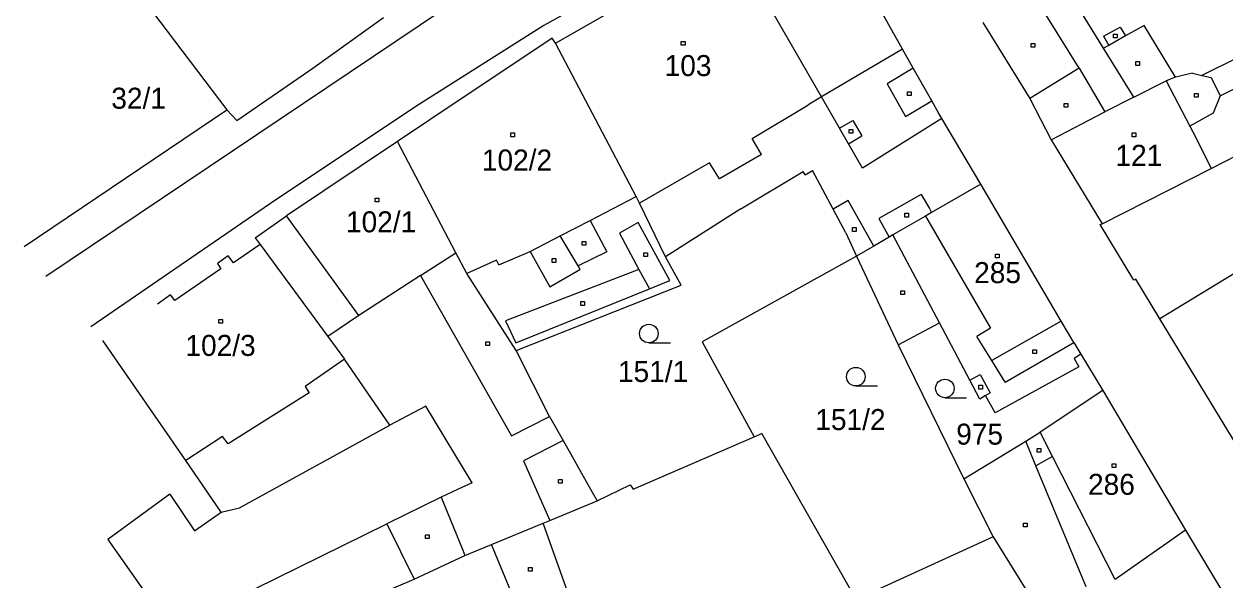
# Model space of a CAD drawing. Extents: x -711879 to -711361, y -1048782 to -1048177.
# Drawn here: x -711816.1 to -711718.9, y -1048658.1 to -1048613.1 of the extents above; entities that cross this region are included whole.
import ezdxf

# ---------------------------------------------------------------- set-up
doc = ezdxf.new("R2010")
doc.units = 0
for name, color, linetype in [('Vrstva 1', 7, 'Continuous'), ('Vrstva 14', 7, 'Continuous'), ('Vrstva 15', 7, 'Continuous'), ('Vrstva 2', 7, 'Continuous'), ('Vrstva 23', 7, 'Continuous'), ('Vrstva 25', 7, 'Continuous'), ('Vrstva 46', 7, 'Continuous')]:
    doc.layers.add(name, color=color, linetype=linetype)

msp = doc.modelspace()

# ---------------------------------------------------------------- linework, layer by layer
at = {"layer": 'Vrstva 1'}
for p, q in [((-711744.94, -1048615.17), (-711751.91, -1048602.81)), ((-711773.03, -1048614.7), (-711758.74, -1048606.51)), ((-711751.49, -1048619.05), (-711758.65, -1048606.65)), ((-711728.66, -1048615.1), (-711732.3, -1048609.22)), ((-711806.26, -1048611.37), (-711799.65, -1048620.09)), ((-711792.69, -1048616.72), (-711786.97, -1048612.61)), ((-711738.43, -1048613.03), (-711734.62, -1048619.17)), ((-711773.3, -1048614.29), (-711783.21, -1048620.9)), ((-711773.03, -1048614.7), (-711773.3, -1048614.29)), ((-711766.51, -1048627.1), (-711773.03, -1048614.7)), ((-711744.07, -1048616.71), (-711744.94, -1048615.17)), ((-711726.2, -1048619.07), (-711728.66, -1048615.1)), ((-711798.83, -1048620.94), (-711792.69, -1048616.72)), ((-711742.57, -1048619.36), (-711744.07, -1048616.71)), ((-711717.7, -1048615.82), (-711720.7, -1048617.31)), ((-711726.2, -1048619.07), (-711723.6, -1048617.74)), ((-711722.84, -1048617.45), (-711723.6, -1048617.74)), ((-711721.47, -1048617.13), (-711722.84, -1048617.45)), ((-711721.47, -1048617.13), (-711720.7, -1048617.31)), ((-711719.96, -1048624.83), (-711707.96, -1048618.7)), ((-711750.04, -1048621.56), (-711751.49, -1048619.05)), ((-711741.99, -1048620.39), (-711742.57, -1048619.36)), ((-711734.62, -1048619.17), (-711732.9, -1048622.51)), ((-711726.2, -1048619.07), (-711728.56, -1048620.25)), ((-711816.07, -1048631.14), (-711799.65, -1048620.09)), ((-711799.65, -1048620.09), (-711798.83, -1048620.94)), ((-711741.76, -1048620.78), (-711741.99, -1048620.39)), ((-711732.9, -1048622.51), (-711728.56, -1048620.25)), ((-711783.21, -1048620.9), (-711785.83, -1048622.65)), ((-711749.3, -1048622.85), (-711750.04, -1048621.56)), ((-711741.76, -1048620.78), (-711748.17, -1048624.8)), ((-711738.61, -1048626.11), (-711741.76, -1048620.78)), ((-711732.9, -1048622.51), (-711728.77, -1048629.3)), ((-711785.83, -1048622.65), (-711794.82, -1048628.67)), ((-711781.1, -1048631.65), (-711785.83, -1048622.65)), ((-711748.17, -1048624.8), (-711749.3, -1048622.85)), ((-711758.03, -1048628.11), (-711752.99, -1048625.07)), ((-711752.83, -1048625.35), (-711752.99, -1048625.07)), ((-711752.83, -1048625.35), (-711752.24, -1048625)), ((-711750.56, -1048628.12), (-711752.24, -1048625)), ((-711728.77, -1048629.3), (-711719.96, -1048624.83)), ((-711738.61, -1048626.11), (-711742.58, -1048628.4)), ((-711732.1, -1048637.18), (-711738.61, -1048626.11)), ((-711766.23, -1048627.63), (-711766.51, -1048627.1)), ((-711764.13, -1048631.98), (-711766.23, -1048627.63)), ((-711758.03, -1048628.11), (-711764.13, -1048631.98)), ((-711749.53, -1048630.05), (-711750.56, -1048628.12)), ((-711742.58, -1048628.4), (-711743.07, -1048628.68)), ((-711797.34, -1048630.45), (-711794.82, -1048628.67)), ((-711743.07, -1048628.68), (-711745.72, -1048630.21)), ((-711728.94, -1048629.38), (-711728.77, -1048629.3)), ((-711726.21, -1048633.88), (-711728.94, -1048629.38)), ((-711711.1, -1048629.08), (-711724.1, -1048636.99)), ((-711749.53, -1048630.05), (-711748.66, -1048631.92)), ((-711746.02, -1048630.38), (-711747.26, -1048631.11)), ((-711745.72, -1048630.21), (-711746.02, -1048630.38)), ((-711796.94, -1048630.99), (-711799.12, -1048632.47)), ((-711797.34, -1048630.45), (-711796.94, -1048630.99)), ((-711796.94, -1048630.99), (-711791.47, -1048638.43)), ((-711747.26, -1048631.11), (-711748.66, -1048631.92)), ((-711799.53, -1048631.89), (-711800.4, -1048632.53)), ((-711799.12, -1048632.47), (-711799.53, -1048631.89)), ((-711780.21, -1048633.34), (-711781.1, -1048631.65)), ((-711762.87, -1048634.28), (-711764.13, -1048631.98)), ((-711748.66, -1048631.92), (-711761.17, -1048638.85)), ((-711748.66, -1048631.92), (-711745.29, -1048639.11)), ((-711800.12, -1048632.96), (-711803.87, -1048635.51)), ((-711800.4, -1048632.53), (-711800.12, -1048632.96)), ((-711776.21, -1048639.55), (-711780.21, -1048633.34)), ((-711726.04, -1048633.8), (-711726.21, -1048633.88)), ((-711724.1, -1048636.99), (-711726.04, -1048633.8)), ((-711804.21, -1048635.06), (-711805.25, -1048635.82)), ((-711803.87, -1048635.51), (-711804.21, -1048635.06)), ((-711776.21, -1048639.55), (-711762.87, -1048634.28)), ((-711731.08, -1048638.91), (-711732.1, -1048637.18)), ((-711717.47, -1048647.9), (-711724.1, -1048636.99)), ((-711745.29, -1048639.11), (-711741.95, -1048637.33)), ((-711739.5, -1048641.97), (-711741.95, -1048637.33)), ((-711802.98, -1048648.46), (-711809.68, -1048638.76)), ((-711791.47, -1048638.43), (-711790.13, -1048640.26)), ((-711761.17, -1048638.85), (-711756.96, -1048646.56)), ((-711745.29, -1048639.11), (-711739.97, -1048649.94)), ((-711731.08, -1048638.91), (-711730.51, -1048639.87)), ((-711773.53, -1048644.89), (-711776.21, -1048639.55)), ((-711730.51, -1048639.87), (-711731.04, -1048640.22)), ((-711730.51, -1048639.87), (-711728.73, -1048642.81)), ((-711786.45, -1048645.6), (-711790.13, -1048640.26)), ((-711730.66, -1048640.89), (-711737.44, -1048644.6)), ((-711731.04, -1048640.22), (-711730.66, -1048640.89)), ((-711738.69, -1048643.5), (-711739.5, -1048641.97)), ((-711728.73, -1048642.81), (-711733.79, -1048646.18)), ((-711728.73, -1048642.81), (-711722.03, -1048654.1)), ((-711738.22, -1048643.21), (-711738.69, -1048643.5)), ((-711737.44, -1048644.6), (-711738.22, -1048643.21)), ((-711783.53, -1048644.06), (-711786.45, -1048645.6)), ((-711779.78, -1048650.28), (-711783.53, -1048644.06)), ((-711773.53, -1048644.89), (-711772.42, -1048646.85)), ((-711798.61, -1048652.29), (-711786.45, -1048645.6)), ((-711772.42, -1048646.85), (-711770.06, -1048651.03)), ((-711766.76, -1048650.79), (-711756.96, -1048646.56)), ((-711756.96, -1048646.56), (-711756.32, -1048646.29)), ((-711748.69, -1048659.7), (-711756.32, -1048646.29)), ((-711739.97, -1048649.94), (-711734.95, -1048646.89)), ((-711734.95, -1048646.89), (-711733.79, -1048646.18)), ((-711800.1, -1048652.63), (-711802.98, -1048648.46)), ((-711780.91, -1048650.79), (-711782.28, -1048651.42)), ((-711779.78, -1048650.28), (-711780.91, -1048650.79)), ((-711769.66, -1048651.73), (-711766.98, -1048650.44)), ((-711766.98, -1048650.44), (-711766.76, -1048650.79)), ((-711739.97, -1048649.94), (-711737.61, -1048654.63)), ((-711782.28, -1048651.42), (-711786.69, -1048653.59)), ((-711773.5, -1048653.31), (-711769.66, -1048651.73)), ((-711770.06, -1048651.03), (-711769.66, -1048651.73)), ((-711800.1, -1048652.63), (-711798.61, -1048652.29)), ((-711786.69, -1048653.59), (-711784.49, -1048658.06)), ((-711778.21, -1048655.25), (-711774.04, -1048653.53)), ((-711774.04, -1048653.53), (-711773.5, -1048653.31)), ((-711771.92, -1048659.43), (-711774.04, -1048653.53)), ((-711737.61, -1048654.63), (-711748.69, -1048659.7)), ((-711737.61, -1048654.63), (-711734.47, -1048659.69)), ((-711722.03, -1048654.1), (-711717.9, -1048660.95)), ((-711780.37, -1048656.14), (-711778.21, -1048655.25)), ((-711784.49, -1048658.06), (-711780.37, -1048656.14)), ((-711792.84, -1048661.61), (-711784.49, -1048658.06))]:
    msp.add_line(p, q, dxfattribs=at)
at = {"layer": 'Vrstva 2'}
for p, q in [((-711759.6, -1048605.21), (-711773.98, -1048613.26)), ((-711730.65, -1048616.71), (-711734.44, -1048610.58)), ((-711814.29, -1048633.54), (-711782.1, -1048611.94)), ((-711773.98, -1048613.26), (-711784.05, -1048619.64)), ((-711728.66, -1048614.13), (-711727.32, -1048613.39)), ((-711727.32, -1048613.39), (-711726.88, -1048614.11)), ((-711725.37, -1048613.27), (-711726.88, -1048614.11)), ((-711722.84, -1048617.45), (-711725.37, -1048613.27)), ((-711728.66, -1048614.13), (-711728.24, -1048614.87)), ((-711726.88, -1048614.11), (-711728.24, -1048614.87)), ((-711744.94, -1048615.17), (-711751.49, -1048619.05)), ((-711728.24, -1048614.87), (-711728.66, -1048615.1)), ((-711744.07, -1048616.71), (-711746.18, -1048617.99)), ((-711730.65, -1048616.71), (-711734.62, -1048619.17)), ((-711730.65, -1048616.71), (-711728.56, -1048620.25)), ((-711723.6, -1048617.74), (-711721.67, -1048621.42)), ((-711720.7, -1048617.31), (-711719.96, -1048617.48)), ((-711719.96, -1048617.48), (-711719.23, -1048618.96)), ((-711719.23, -1048618.96), (-711716.76, -1048617.74)), ((-711746.18, -1048617.99), (-711744.69, -1048620.63)), ((-711784.05, -1048619.64), (-711795.68, -1048627.37)), ((-711751.49, -1048619.05), (-711752.6, -1048619.71)), ((-711744.69, -1048620.63), (-711742.57, -1048619.36)), ((-711719.23, -1048618.96), (-711719.79, -1048620.36)), ((-711757.12, -1048622.42), (-711752.6, -1048619.71)), ((-711719.79, -1048620.36), (-711721.67, -1048621.42)), ((-711750.04, -1048621.56), (-711748.96, -1048620.94)), ((-711748.96, -1048620.94), (-711748.24, -1048622.19)), ((-711721.67, -1048621.42), (-711721.19, -1048622.34)), ((-711756.37, -1048623.69), (-711757.12, -1048622.42)), ((-711749.3, -1048622.85), (-711748.24, -1048622.19)), ((-711721.19, -1048622.34), (-711719.96, -1048624.83)), ((-711760.57, -1048624.37), (-711766.23, -1048627.63)), ((-711759.76, -1048625.67), (-711760.57, -1048624.37)), ((-711756.37, -1048623.69), (-711759.76, -1048625.67)), ((-711795.68, -1048627.37), (-711810.66, -1048637.64)), ((-711770.23, -1048629.03), (-711766.51, -1048627.1)), ((-711749.33, -1048627.42), (-711750.56, -1048628.12)), ((-711747.26, -1048631.11), (-711749.33, -1048627.42)), ((-711743.42, -1048626.93), (-711746.85, -1048628.88)), ((-711743.42, -1048626.93), (-711742.76, -1048628.07)), ((-711742.76, -1048628.07), (-711742.58, -1048628.4)), ((-711788.95, -1048636.74), (-711794.82, -1048628.67)), ((-711772.65, -1048630.28), (-711770.23, -1048629.03)), ((-711770.23, -1048629.03), (-711768.89, -1048631.59)), ((-711766.34, -1048629.21), (-711767.86, -1048630.06)), ((-711763.79, -1048633.9), (-711766.34, -1048629.21)), ((-711746.85, -1048628.88), (-711746.02, -1048630.38)), ((-711743.07, -1048628.68), (-711737.82, -1048637.75)), ((-711775.1, -1048631.55), (-711772.65, -1048630.28)), ((-711771.21, -1048632.71), (-711772.65, -1048630.28)), ((-711767.86, -1048630.06), (-711766.29, -1048633.02)), ((-711741.95, -1048637.33), (-711745.72, -1048630.21)), ((-711783.96, -1048633.5), (-711781.1, -1048631.65)), ((-711777.82, -1048632.24), (-711780.21, -1048633.34)), ((-711777.63, -1048632.63), (-711777.82, -1048632.24)), ((-711777.63, -1048632.63), (-711775.1, -1048631.55)), ((-711775.1, -1048631.55), (-711773.49, -1048634.41)), ((-711768.89, -1048631.59), (-711771.21, -1048632.71)), ((-711766.29, -1048633.02), (-711777.09, -1048637.15)), ((-711773.49, -1048634.41), (-711771.06, -1048633.02)), ((-711771.21, -1048632.71), (-711771.06, -1048633.02)), ((-711766.29, -1048633.02), (-711765.42, -1048634.58)), ((-711783.96, -1048633.5), (-711788.95, -1048636.74)), ((-711783.96, -1048633.5), (-711776.59, -1048646.46)), ((-711765.42, -1048634.58), (-711763.79, -1048633.9)), ((-711776.24, -1048638.93), (-711765.42, -1048634.58)), ((-711788.95, -1048636.74), (-711791.47, -1048638.43)), ((-711777.09, -1048637.15), (-711776.24, -1048638.93)), ((-711732.1, -1048637.18), (-711737.71, -1048640.37)), ((-711737.82, -1048637.75), (-711738.91, -1048638.43)), ((-711737.71, -1048640.37), (-711738.91, -1048638.43)), ((-711736.64, -1048642.12), (-711731.08, -1048638.91)), ((-711790.13, -1048640.26), (-711793.3, -1048642.47)), ((-711736.64, -1048642.12), (-711737.71, -1048640.37)), ((-711739.5, -1048641.97), (-711738.64, -1048641.5)), ((-711738.64, -1048641.5), (-711737.84, -1048642.98)), ((-711792.98, -1048642.98), (-711799.55, -1048647.12)), ((-711793.3, -1048642.47), (-711792.98, -1048642.98)), ((-711738.22, -1048643.21), (-711737.84, -1048642.98)), ((-711776.59, -1048646.46), (-711773.53, -1048644.89)), ((-711800.01, -1048646.52), (-711802.98, -1048648.46)), ((-711799.55, -1048647.12), (-711800.01, -1048646.52)), ((-711772.42, -1048646.85), (-711775.64, -1048648.48)), ((-711734.14, -1048648.9), (-711734.95, -1048646.89)), ((-711732.79, -1048648.14), (-711733.79, -1048646.18)), ((-711775.64, -1048648.48), (-711773.5, -1048653.31)), ((-711732.79, -1048648.14), (-711734.14, -1048648.9)), ((-711727.73, -1048658.09), (-711732.79, -1048648.14)), ((-711730.06, -1048658.68), (-711734.14, -1048648.9)), ((-711804.26, -1048651.18), (-711809.27, -1048654.86)), ((-711804.26, -1048651.18), (-711802.27, -1048654.16)), ((-711782.28, -1048651.42), (-711780.54, -1048655.73)), ((-711802.27, -1048654.16), (-711800.1, -1048652.63)), ((-711799.14, -1048659.71), (-711786.69, -1048653.59)), ((-711722.03, -1048654.1), (-711727.73, -1048658.09)), ((-711809.27, -1048654.86), (-711804.42, -1048661.76)), ((-711776.33, -1048659.82), (-711778.21, -1048655.25)), ((-711780.54, -1048655.73), (-711780.37, -1048656.14))]:
    msp.add_line(p, q, dxfattribs=at)
at = {"layer": 'Vrstva 23'}
for p, q in [((-711765.48, -1048638.94), (-711763.73, -1048638.94)), ((-711748.72, -1048642.43), (-711746.97, -1048642.43)), ((-711741.51, -1048643.38), (-711739.76, -1048643.38))]:
    msp.add_line(p, q, dxfattribs=at)
for centre in [(-711765.48, -1048638.19), (-711748.72, -1048641.68), (-711741.51, -1048642.63)]:
    msp.add_circle(centre, 0.75, dxfattribs=at)
at = {"layer": 'Vrstva 25'}
for p, q in [((-711762.85, -1048614.55), (-711762.55, -1048614.55)), ((-711762.85, -1048614.85), (-711762.85, -1048614.55)), ((-711762.55, -1048614.55), (-711762.55, -1048614.85)), ((-711734.53, -1048614.72), (-711734.23, -1048614.72)), ((-711734.53, -1048615.02), (-711734.53, -1048614.72)), ((-711734.23, -1048614.72), (-711734.23, -1048615.02)), ((-711727.86, -1048613.97), (-711727.56, -1048613.97)), ((-711727.86, -1048614.27), (-711727.86, -1048613.97)), ((-711727.56, -1048614.27), (-711727.86, -1048614.27)), ((-711727.56, -1048613.97), (-711727.56, -1048614.27)), ((-711762.55, -1048614.85), (-711762.85, -1048614.85)), ((-711734.23, -1048615.02), (-711734.53, -1048615.02)), ((-711726.05, -1048616.19), (-711725.75, -1048616.19)), ((-711726.05, -1048616.49), (-711726.05, -1048616.19)), ((-711725.75, -1048616.49), (-711726.05, -1048616.49)), ((-711725.75, -1048616.19), (-711725.75, -1048616.49)), ((-711744.54, -1048618.64), (-711744.24, -1048618.64)), ((-711744.54, -1048618.94), (-711744.54, -1048618.64)), ((-711744.24, -1048618.64), (-711744.24, -1048618.94)), ((-711744.24, -1048618.94), (-711744.54, -1048618.94)), ((-711731.86, -1048619.57), (-711731.56, -1048619.57)), ((-711731.86, -1048619.87), (-711731.86, -1048619.57)), ((-711731.56, -1048619.57), (-711731.56, -1048619.87)), ((-711721.3, -1048618.76), (-711721, -1048618.76)), ((-711721.3, -1048619.06), (-711721.3, -1048618.76)), ((-711721, -1048619.06), (-711721.3, -1048619.06)), ((-711721, -1048618.76), (-711721, -1048619.06)), ((-711731.56, -1048619.87), (-711731.86, -1048619.87)), ((-711776.66, -1048621.96), (-711776.36, -1048621.96)), ((-711776.66, -1048622.26), (-711776.66, -1048621.96)), ((-711776.36, -1048622.26), (-711776.66, -1048622.26)), ((-711776.36, -1048621.96), (-711776.36, -1048622.26)), ((-711749.25, -1048621.67), (-711748.95, -1048621.67)), ((-711749.25, -1048621.97), (-711749.25, -1048621.67)), ((-711748.95, -1048621.97), (-711749.25, -1048621.97)), ((-711748.95, -1048621.67), (-711748.95, -1048621.97)), ((-711726.35, -1048621.96), (-711726.05, -1048621.96)), ((-711726.35, -1048622.26), (-711726.35, -1048621.96)), ((-711726.05, -1048622.26), (-711726.35, -1048622.26)), ((-711726.05, -1048621.96), (-711726.05, -1048622.26)), ((-711787.65, -1048627.24), (-711787.35, -1048627.24)), ((-711787.65, -1048627.54), (-711787.65, -1048627.24)), ((-711787.35, -1048627.24), (-711787.35, -1048627.54)), ((-711787.35, -1048627.54), (-711787.65, -1048627.54)), ((-711744.75, -1048628.46), (-711744.45, -1048628.46)), ((-711744.75, -1048628.76), (-711744.75, -1048628.46)), ((-711744.45, -1048628.76), (-711744.75, -1048628.76)), ((-711744.45, -1048628.46), (-711744.45, -1048628.76)), ((-711749, -1048629.62), (-711748.7, -1048629.62)), ((-711749, -1048629.92), (-711749, -1048629.62)), ((-711748.7, -1048629.92), (-711749, -1048629.92)), ((-711748.7, -1048629.62), (-711748.7, -1048629.92)), ((-711770.87, -1048630.74), (-711770.57, -1048630.74)), ((-711770.87, -1048631.04), (-711770.87, -1048630.74)), ((-711770.57, -1048631.04), (-711770.87, -1048631.04)), ((-711770.57, -1048630.74), (-711770.57, -1048631.04)), ((-711773.31, -1048632.13), (-711773.01, -1048632.13)), ((-711773.31, -1048632.43), (-711773.31, -1048632.13)), ((-711773.01, -1048632.13), (-711773.01, -1048632.43)), ((-711765.89, -1048631.66), (-711765.59, -1048631.66)), ((-711765.89, -1048631.96), (-711765.89, -1048631.66)), ((-711765.59, -1048631.96), (-711765.89, -1048631.96)), ((-711765.59, -1048631.66), (-711765.59, -1048631.96)), ((-711737.42, -1048631.76), (-711737.12, -1048631.76)), ((-711737.42, -1048632.06), (-711737.42, -1048631.76)), ((-711737.12, -1048632.06), (-711737.42, -1048632.06)), ((-711737.12, -1048631.76), (-711737.12, -1048632.06)), ((-711773.01, -1048632.43), (-711773.31, -1048632.43)), ((-711745.07, -1048634.73), (-711744.77, -1048634.73)), ((-711745.07, -1048635.03), (-711745.07, -1048634.73)), ((-711744.77, -1048635.03), (-711745.07, -1048635.03)), ((-711744.77, -1048634.73), (-711744.77, -1048635.03)), ((-711770.99, -1048635.61), (-711770.69, -1048635.61)), ((-711770.99, -1048635.91), (-711770.99, -1048635.61)), ((-711770.69, -1048635.91), (-711770.99, -1048635.91)), ((-711770.69, -1048635.61), (-711770.69, -1048635.91)), ((-711800.29, -1048637.06), (-711799.99, -1048637.06)), ((-711800.29, -1048637.36), (-711800.29, -1048637.06)), ((-711799.99, -1048637.06), (-711799.99, -1048637.36)), ((-711799.99, -1048637.36), (-711800.29, -1048637.36)), ((-711778.69, -1048638.87), (-711778.39, -1048638.87)), ((-711778.69, -1048639.17), (-711778.69, -1048638.87)), ((-711778.39, -1048638.87), (-711778.39, -1048639.17)), ((-711778.39, -1048639.17), (-711778.69, -1048639.17)), ((-711734.4, -1048639.51), (-711734.1, -1048639.51)), ((-711734.4, -1048639.81), (-711734.4, -1048639.51)), ((-711734.1, -1048639.81), (-711734.4, -1048639.81)), ((-711734.1, -1048639.51), (-711734.1, -1048639.81)), ((-711738.76, -1048642.38), (-711738.46, -1048642.38)), ((-711738.76, -1048642.68), (-711738.76, -1048642.38)), ((-711738.46, -1048642.68), (-711738.76, -1048642.68)), ((-711738.46, -1048642.38), (-711738.46, -1048642.68)), ((-711734.04, -1048647.48), (-711733.74, -1048647.48)), ((-711734.04, -1048647.78), (-711734.04, -1048647.48)), ((-711733.74, -1048647.78), (-711734.04, -1048647.78)), ((-711733.74, -1048647.48), (-711733.74, -1048647.78)), ((-711727.97, -1048648.74), (-711727.67, -1048648.74)), ((-711727.97, -1048649.04), (-711727.97, -1048648.74)), ((-711727.67, -1048648.74), (-711727.67, -1048649.04)), ((-711727.67, -1048649.04), (-711727.97, -1048649.04)), ((-711772.79, -1048649.99), (-711772.49, -1048649.99)), ((-711772.79, -1048650.29), (-711772.79, -1048649.99)), ((-711772.49, -1048650.29), (-711772.79, -1048650.29)), ((-711772.49, -1048649.99), (-711772.49, -1048650.29)), ((-711735.14, -1048653.53), (-711734.84, -1048653.53)), ((-711735.14, -1048653.83), (-711735.14, -1048653.53)), ((-711734.84, -1048653.53), (-711734.84, -1048653.83)), ((-711783.56, -1048654.47), (-711783.26, -1048654.47)), ((-711783.56, -1048654.77), (-711783.56, -1048654.47)), ((-711783.26, -1048654.47), (-711783.26, -1048654.77)), ((-711734.84, -1048653.83), (-711735.14, -1048653.83)), ((-711783.26, -1048654.77), (-711783.56, -1048654.77)), ((-711775.22, -1048657.11), (-711774.92, -1048657.11)), ((-711775.22, -1048657.41), (-711775.22, -1048657.11)), ((-711774.92, -1048657.41), (-711775.22, -1048657.41)), ((-711774.92, -1048657.11), (-711774.92, -1048657.41))]:
    msp.add_line(p, q, dxfattribs=at)
at = {"layer": 'Vrstva 46'}
for p, q in [((-711728.66, -1048615.1), (-711728.66, -1048615.1)), ((-711792.69, -1048616.72), (-711792.69, -1048616.72)), ((-711730.65, -1048616.71), (-711730.65, -1048616.71)), ((-711723.6, -1048617.74), (-711723.6, -1048617.74)), ((-711721.47, -1048617.13), (-711721.47, -1048617.13)), ((-711720.7, -1048617.31), (-711720.7, -1048617.31)), ((-711719.96, -1048617.48), (-711719.96, -1048617.48)), ((-711734.62, -1048619.17), (-711734.62, -1048619.17)), ((-711726.2, -1048619.07), (-711726.2, -1048619.07)), ((-711719.23, -1048618.96), (-711719.23, -1048618.96)), ((-711732.9, -1048622.51), (-711732.9, -1048622.51)), ((-711756.37, -1048623.69), (-711756.37, -1048623.69)), ((-711719.96, -1048624.83), (-711719.96, -1048624.83)), ((-711759.76, -1048625.67), (-711759.76, -1048625.67)), ((-711758.03, -1048628.11), (-711758.03, -1048628.11)), ((-711728.94, -1048629.38), (-711728.94, -1048629.38)), ((-711728.77, -1048629.3), (-711728.77, -1048629.3)), ((-711775.1, -1048631.55), (-711775.1, -1048631.55)), ((-711777.63, -1048632.63), (-711777.63, -1048632.63)), ((-711771.06, -1048633.02), (-711771.06, -1048633.02)), ((-711783.96, -1048633.5), (-711783.96, -1048633.5)), ((-711780.21, -1048633.34), (-711780.21, -1048633.34)), ((-711773.49, -1048634.41), (-711773.49, -1048634.41)), ((-711788.95, -1048636.74), (-711788.95, -1048636.74)), ((-711724.1, -1048636.99), (-711724.1, -1048636.99)), ((-711776.21, -1048639.55), (-711776.21, -1048639.55)), ((-711790.13, -1048640.26), (-711790.13, -1048640.26)), ((-711783.53, -1048644.06), (-711783.53, -1048644.06)), ((-711773.53, -1048644.89), (-711773.53, -1048644.89)), ((-711786.45, -1048645.6), (-711786.45, -1048645.6)), ((-711776.59, -1048646.46), (-711776.59, -1048646.46)), ((-711772.42, -1048646.85), (-711772.42, -1048646.85)), ((-711780.91, -1048650.79), (-711780.91, -1048650.79)), ((-711779.78, -1048650.28), (-711779.78, -1048650.28)), ((-711804.26, -1048651.18), (-711804.26, -1048651.18)), ((-711782.28, -1048651.42), (-711782.28, -1048651.42)), ((-711770.06, -1048651.03), (-711770.06, -1048651.03)), ((-711769.66, -1048651.73), (-711769.66, -1048651.73)), ((-711800.1, -1048652.63), (-711800.1, -1048652.63)), ((-711786.69, -1048653.59), (-711786.69, -1048653.59)), ((-711802.27, -1048654.16), (-711802.27, -1048654.16)), ((-711780.54, -1048655.73), (-711780.54, -1048655.73)), ((-711780.37, -1048656.14), (-711780.37, -1048656.14)), ((-711784.49, -1048658.06), (-711784.49, -1048658.06)), ((-711727.73, -1048658.09), (-711727.73, -1048658.09))]:
    msp.add_line(p, q, dxfattribs=at)

# ---------------------------------------------------------------- texts
at = {"layer": 'Vrstva 14'}
for s, p in [('151/1', (-711767.98, -1048642.11)), ('151/2', (-711752, -1048646)), ('975', (-711740.59, -1048647.18))]:
    msp.add_text(s, height=1.7, dxfattribs=at).set_placement(p)
at = {"layer": 'Vrstva 15'}
for s, p in [('103', (-711764.2, -1048617.36)), ('32/1', (-711809, -1048620)), ('102/2', (-711779, -1048625)), ('121', (-711727.7, -1048624.62)), ('102/1', (-711790, -1048630)), ('285', (-711739.14, -1048634.11)), ('102/3', (-711803, -1048640)), ('286', (-711729.92, -1048651.24))]:
    msp.add_text(s, height=1.7, dxfattribs=at).set_placement(p)

doc.saveas('drawing.dxf')
